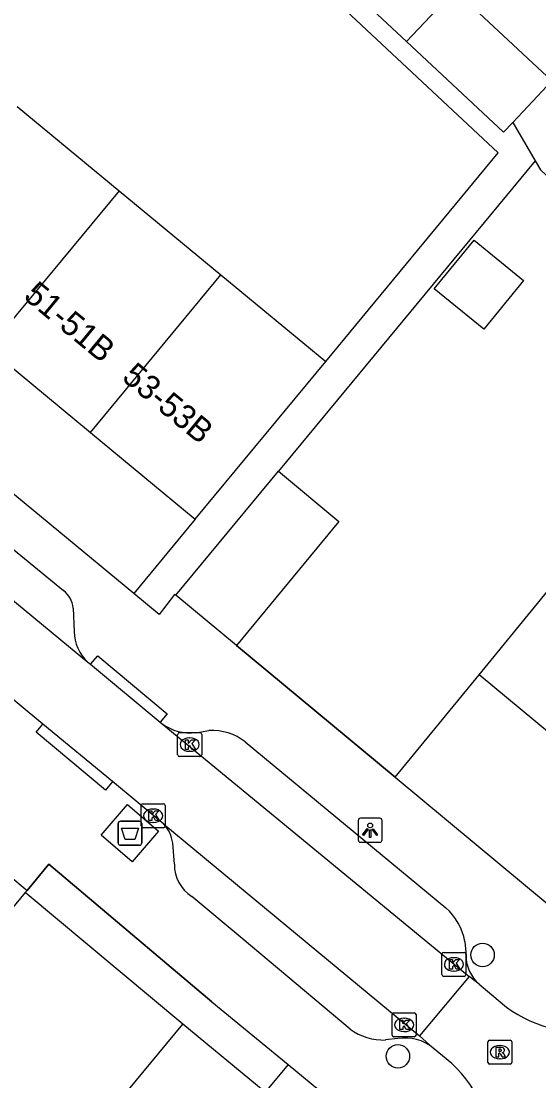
# Model space of a CAD drawing. Extents: x 162074 to 163034, y 381824 to 382557.
# Drawn here: x 162580.7 to 162602.27, y 382130.62 to 382174.8 of the extents above; entities that cross this region are included whole.
import ezdxf

# ---------------------------------------------------------------- set-up
doc = ezdxf.new("R2010")
doc.units = 0
for name, color, linetype in [('IMGEO_Afval_apart_plaats', 7, 'Continuous'), ('IMGEO_Boom', 7, 'Continuous'), ('IMGEO_Kolk', 7, 'Continuous'), ('IMGEO_Lichtpunt', 7, 'Continuous'), ('IMGEO_Muur', 7, 'Continuous'), ('IMGEO_Pand', 7, 'Continuous'), ('IMGEO_Pand_nummerreeks', 7, 'Continuous'), ('IMGEO_Rijbaan_lokaal_open', 7, 'Continuous'), ('IMGEO_Rioolput', 7, 'Continuous'), ('IMGEO_Voetpad_gesloten', 7, 'Continuous'), ('IMGEO_Voetpad_open', 7, 'Continuous')]:
    doc.layers.add(name, color=color, linetype=linetype)

msp = doc.modelspace()

# ---------------------------------------------------------------- linework, layer by layer
at = {"layer": 'IMGEO_Afval_apart_plaats'}
for p, q in [((162584.736, 382140.54), (162584.736, 382141.34)), ((162584.736, 382141.34), (162584.736, 382140.54)), ((162584.836, 382141.44), (162585.626, 382141.44)), ((162585.626, 382141.44), (162584.836, 382141.44)), ((162585.726, 382141.34), (162585.726, 382140.54)), ((162585.726, 382140.54), (162585.726, 382141.34)), ((162585.626, 382140.44), (162584.836, 382140.44)), ((162584.836, 382140.44), (162585.626, 382140.44))]:
    msp.add_line(p, q, dxfattribs=at)
msp.add_lwpolyline([(162584.879, 382141.154), (162585.583, 382141.154), (162585.434, 382140.684), (162585.028, 382140.684), (162584.879, 382141.154)], dxfattribs=at)
for centre, start, end in [((162584.836, 382141.34), 90, 180), ((162584.836, 382141.34), 90, 180), ((162585.626, 382141.34), 0, 90), ((162585.626, 382141.34), 360, 90), ((162584.836, 382140.54), 180, 270), ((162584.836, 382140.54), 180, 270), ((162585.626, 382140.54), 270, 0), ((162585.626, 382140.54), 270, 0)]:
    msp.add_arc(centre, 0.1, start, end, dxfattribs=at)
at = {"layer": 'IMGEO_Boom'}
for centre in [(162599.932, 382135.864), (162596.402, 382131.638)]:
    msp.add_circle(centre, 0.489, dxfattribs=at)
at = {"layer": 'IMGEO_Kolk'}
for p, q in [((162587.297, 382145.137), (162588.149, 382145.137)), ((162587.222, 382144.211), (162587.222, 382145.063)), ((162587.71, 382144.917), (162587.735, 382144.917)), ((162588.223, 382145.063), (162588.223, 382144.211)), ((162587.733, 382144.357), (162587.708, 382144.357)), ((162588.149, 382144.137), (162587.297, 382144.137)), ((162585.704, 382141.243), (162585.704, 382142.095)), ((162585.779, 382142.169), (162586.631, 382142.169)), ((162586.705, 382142.095), (162586.705, 382141.243)), ((162586.192, 382141.949), (162586.217, 382141.949)), ((162586.631, 382141.169), (162585.779, 382141.169)), ((162586.215, 382141.389), (162586.19, 382141.389)), ((162598.238, 382135.045), (162598.238, 382135.897)), ((162598.313, 382135.971), (162599.165, 382135.971)), ((162599.239, 382135.897), (162599.239, 382135.045)), ((162598.726, 382135.751), (162598.751, 382135.751)), ((162599.165, 382134.971), (162598.313, 382134.971)), ((162598.749, 382135.191), (162598.724, 382135.191)), ((162596.158, 382132.523), (162596.158, 382133.375)), ((162596.233, 382133.449), (162597.085, 382133.449)), ((162596.646, 382133.229), (162596.671, 382133.229)), ((162597.159, 382133.375), (162597.159, 382132.523)), ((162597.085, 382132.449), (162596.233, 382132.449)), ((162596.669, 382132.669), (162596.644, 382132.669))]:
    msp.add_line(p, q, dxfattribs=at)
for points in [[(162587.297, 382145.137), (162588.149, 382145.137)], [(162587.222, 382144.211), (162587.222, 382145.063)], [(162587.543, 382144.837), (162587.666, 382144.837), (162587.666, 382144.686), (162587.796, 382144.837), (162587.96, 382144.837), (162587.814, 382144.686), (162587.967, 382144.437), (162587.815, 382144.437), (162587.73, 382144.601), (162587.666, 382144.534), (162587.666, 382144.437), (162587.543, 382144.437), (162587.543, 382144.837)], [(162588.223, 382145.063), (162588.223, 382144.211)], [(162588.149, 382144.137), (162587.297, 382144.137)], [(162585.704, 382141.243), (162585.704, 382142.095)], [(162585.779, 382142.169), (162586.631, 382142.169)], [(162586.705, 382142.095), (162586.705, 382141.243)], [(162586.025, 382141.869), (162586.148, 382141.869), (162586.148, 382141.718), (162586.278, 382141.869), (162586.442, 382141.869), (162586.296, 382141.718), (162586.449, 382141.469), (162586.297, 382141.469), (162586.212, 382141.633), (162586.148, 382141.566), (162586.148, 382141.469), (162586.025, 382141.469), (162586.025, 382141.869)], [(162586.631, 382141.169), (162585.779, 382141.169)], [(162598.238, 382135.045), (162598.238, 382135.897)], [(162598.313, 382135.971), (162599.165, 382135.971)], [(162599.239, 382135.897), (162599.239, 382135.045)], [(162598.559, 382135.671), (162598.682, 382135.671), (162598.682, 382135.52), (162598.812, 382135.671), (162598.976, 382135.671), (162598.83, 382135.52), (162598.983, 382135.271), (162598.831, 382135.271), (162598.746, 382135.435), (162598.682, 382135.368), (162598.682, 382135.271), (162598.559, 382135.271), (162598.559, 382135.671)], [(162599.165, 382134.971), (162598.313, 382134.971)], [(162596.158, 382132.523), (162596.158, 382133.375)], [(162596.233, 382133.449), (162597.085, 382133.449)], [(162596.479, 382133.149), (162596.602, 382133.149), (162596.602, 382132.998), (162596.732, 382133.149), (162596.896, 382133.149), (162596.75, 382132.998), (162596.903, 382132.749), (162596.751, 382132.749), (162596.666, 382132.913), (162596.602, 382132.846), (162596.602, 382132.749), (162596.479, 382132.749), (162596.479, 382133.149)], [(162597.159, 382133.375), (162597.159, 382132.523)], [(162597.085, 382132.449), (162596.233, 382132.449)]]:
    msp.add_lwpolyline(points, dxfattribs=at)
for centre, start, end in [((162587.299, 382145.061), 91.552, 178.448), ((162587.299, 382145.061), 91.552, 178.448), ((162588.147, 382145.061), 1.552, 88.448), ((162588.147, 382145.061), 1.552, 88.448), ((162587.299, 382144.213), 181.552, 268.448), ((162587.299, 382144.213), 181.552, 268.448), ((162588.147, 382144.213), 271.552, 358.448), ((162588.147, 382144.213), 271.552, 358.448), ((162585.781, 382142.093), 91.552, 178.448), ((162585.781, 382142.093), 91.552, 178.448), ((162586.629, 382142.093), 1.552, 88.448), ((162586.629, 382142.093), 1.552, 88.448), ((162585.781, 382141.245), 181.552, 268.448), ((162585.781, 382141.245), 181.552, 268.448), ((162586.629, 382141.245), 271.552, 358.448), ((162586.629, 382141.245), 271.552, 358.448), ((162598.315, 382135.895), 91.552, 178.448), ((162598.315, 382135.895), 91.552, 178.448), ((162599.163, 382135.895), 1.552, 88.448), ((162599.163, 382135.895), 1.552, 88.448), ((162598.315, 382135.047), 181.552, 268.448), ((162598.315, 382135.047), 181.552, 268.448), ((162599.163, 382135.047), 271.552, 358.448), ((162599.163, 382135.047), 271.552, 358.448), ((162596.235, 382133.373), 91.552, 178.448), ((162596.235, 382133.373), 91.552, 178.448), ((162597.083, 382133.373), 1.552, 88.448), ((162597.083, 382133.373), 1.552, 88.448), ((162596.235, 382132.525), 181.552, 268.448), ((162596.235, 382132.525), 181.552, 268.448), ((162597.083, 382132.525), 271.552, 358.448), ((162597.083, 382132.525), 271.552, 358.448)]:
    msp.add_arc(centre, 0.0765, start, end, dxfattribs=at)
for centre, major_axis, ratio, start_param, end_param in [((162587.709, 382144.637), (-0.387, 0.002), 0.722429, 4.712389, 7.853982), ((162587.734, 382144.637), (-0.39, 0.002), 0.717154, 1.570796, 4.712389), ((162586.191, 382141.669), (-0.387, 0.002), 0.722429, 4.712389, 7.853982), ((162586.216, 382141.669), (-0.39, 0.002), 0.717154, 1.570796, 4.712389), ((162598.725, 382135.471), (-0.387, 0.002), 0.722429, 4.712389, 7.853982), ((162598.75, 382135.471), (-0.39, 0.002), 0.717154, 1.570796, 4.712389), ((162596.645, 382132.949), (-0.387, 0.002), 0.722429, 4.712389, 7.853982), ((162596.67, 382132.949), (-0.39, 0.002), 0.717154, 1.570796, 4.712389)]:
    msp.add_ellipse(centre, major_axis=major_axis, ratio=ratio, start_param=start_param, end_param=end_param, dxfattribs=at)
at = {"layer": 'IMGEO_Lichtpunt'}
for p, q in [((162595.648, 382141.562), (162594.84, 382141.562)), ((162595.648, 382141.562), (162594.84, 382141.562)), ((162594.746, 382141.467), (162594.746, 382140.66)), ((162594.746, 382141.467), (162594.746, 382140.66)), ((162595.742, 382140.66), (162595.742, 382141.467)), ((162595.742, 382140.66), (162595.742, 382141.467)), ((162594.84, 382140.566), (162595.648, 382140.566)), ((162594.84, 382140.566), (162595.648, 382140.566))]:
    msp.add_line(p, q, dxfattribs=at)
for points in [[(162595.12, 382141.131), (162595.159, 382141.103), (162594.971, 382140.841), (162594.933, 382140.868), (162595.12, 382141.131)], [(162595.332, 382141.103), (162595.37, 382141.13), (162595.557, 382140.868), (162595.518, 382140.84), (162595.332, 382141.103)], [(162595.222, 382141.083), (162595.269, 382141.083), (162595.269, 382140.761), (162595.222, 382140.761), (162595.222, 382141.083)]]:
    msp.add_lwpolyline(points, dxfattribs=at)
msp.add_circle((162595.245, 382141.265), 0.0994, dxfattribs=at)
for centre, start, end in [((162594.84, 382141.467), 90, 180), ((162594.84, 382141.467), 90, 180), ((162595.648, 382141.467), 0, 90), ((162595.648, 382141.467), 0, 90), ((162594.84, 382140.66), 180, 270), ((162594.84, 382140.66), 180, 270), ((162595.648, 382140.66), 270, 0), ((162595.648, 382140.66), 270, 360)]:
    msp.add_arc(centre, 0.0946, start, end, dxfattribs=at)
at = {"layer": 'IMGEO_Muur'}
for points in [[(162596.289, 382143.28), (162589.673, 382148.769)], [(162588.643, 382133.909), (162581.857, 382139.648), (162580.943, 382138.549)]]:
    msp.add_lwpolyline(points, dxfattribs=at)
at = {"layer": 'IMGEO_Pand'}
for points in [[(162596.764, 382173.95), (162592.721, 382177.733)], [(162598.774, 382176.098), (162596.764, 382173.95)], [(162598.774, 382176.098), (162602.817, 382172.315)], [(162596.764, 382173.95), (162600.807, 382170.167), (162601.197, 382170.583)], [(162602.817, 382172.315), (162601.812, 382171.241), (162601.197, 382170.583)], [(162602.128, 382168.98), (162602.35, 382168.598), (162603.029, 382167.963), (162605.932, 382171.065), (162605.08, 382171.863), (162602.817, 382172.315)], [(162580.53, 382171.244), (162584.777, 382167.732)], [(162601.197, 382170.583), (162602.128, 382168.98)], [(162584.777, 382167.732), (162579.338, 382161.16)], [(162584.777, 382167.732), (162589.023, 382164.22)], [(162597.919, 382163.646), (162599.578, 382165.671), (162601.641, 382163.982), (162599.982, 382161.956), (162597.919, 382163.646)], [(162583.585, 382157.648), (162589.023, 382164.22)], [(162589.023, 382164.22), (162593.393, 382160.606)], [(162579.338, 382161.16), (162583.585, 382157.648)], [(162587.956, 382154.032), (162593.393, 382160.606)], [(162583.585, 382157.648), (162587.956, 382154.032)], [(162587.149, 382150.868), (162591.419, 382156.031)], [(162591.419, 382156.031), (162593.943, 382153.932), (162589.673, 382148.769)], [(162599.784, 382147.547), (162603.279, 382151.815)], [(162589.673, 382148.769), (162587.149, 382150.868)], [(162596.289, 382143.28), (162599.784, 382147.547)], [(162607.287, 382143.348), (162604.281, 382145.835), (162603.295, 382144.643), (162599.784, 382147.547)], [(162596.289, 382143.28), (162602.791, 382137.875)], [(162578.638, 382140.471), (162580.943, 382138.549)], [(162580.871, 382138.462), (162576.913, 382133.681), (162574.608, 382135.603)], [(162580.871, 382138.462), (162580.943, 382138.549)], [(162583.835, 382128.631), (162587.435, 382132.983)], [(162591.826, 382131.301), (162590.868, 382130.143), (162587.435, 382132.983)], [(162591.826, 382131.301), (162594.946, 382128.72)]]:
    msp.add_lwpolyline(points, dxfattribs=at)
at = {"layer": 'IMGEO_Rijbaan_lokaal_open'}
for points in [[(162455.575, 382254.047), (162467.743, 382243.863), (162583.48, 382148.075)], [(162581.599, 382145.482), (162576.743, 382149.513)], [(162583.48, 382148.075), (162583.59, 382147.984)], [(162583.59, 382147.984), (162586.493, 382145.572)], [(162586.493, 382145.572), (162586.579, 382145.506)], [(162584.507, 382143.092), (162581.599, 382145.482)], [(162586.579, 382145.506), (162599.371, 382134.967)], [(162586.648, 382141.318), (162584.507, 382143.092)], [(162586.648, 382141.318), (162597.298, 382132.492)], [(162599.371, 382134.967), (162597.298, 382132.492)], [(162599.786, 382134.645), (162599.371, 382134.967)], [(162599.786, 382134.645), (162600.923, 382133.683)], [(162597.298, 382132.492), (162597.874, 382131.979)], [(162598.653, 382131.338), (162597.874, 382131.979)]]:
    msp.add_lwpolyline(points, dxfattribs=at)
for centre, radius, start, end in [((162604.179, 382138.227), 5.59, 234.3736, 323.6831), ((162594.493, 382127.015), 6, 321.0212, 46.1023)]:
    msp.add_arc(centre, radius, start, end, dxfattribs=at)
at = {"layer": 'IMGEO_Rioolput'}
for p, q in [((162600.226, 382132.31), (162601.078, 382132.31)), ((162600.151, 382131.384), (162600.151, 382132.236)), ((162600.639, 382132.09), (162600.664, 382132.09)), ((162601.152, 382132.236), (162601.152, 382131.384)), ((162600.662, 382131.53), (162600.637, 382131.53)), ((162601.078, 382131.31), (162600.226, 382131.31))]:
    msp.add_line(p, q, dxfattribs=at)
for points in [[(162600.226, 382132.31), (162601.078, 382132.31)], [(162600.151, 382131.384), (162600.151, 382132.236)], [(162600.74, 382132.008), (162600.488, 382132.01), (162600.488, 382131.61)], [(162600.666, 382131.929), (162600.612, 382131.929), (162600.612, 382131.848)], [(162600.612, 382131.848), (162600.664, 382131.848)], [(162601.152, 382132.236), (162601.152, 382131.384)], [(162600.488, 382131.61), (162600.612, 382131.61), (162600.612, 382131.772), (162600.623, 382131.772)], [(162600.67, 382131.743), (162600.741, 382131.61), (162600.881, 382131.61), (162600.816, 382131.736)], [(162601.078, 382131.31), (162600.226, 382131.31)]]:
    msp.add_lwpolyline(points, dxfattribs=at)
for centre, radius, start, end in [((162600.228, 382132.234), 0.0765, 91.552, 178.448), ((162600.228, 382132.234), 0.0765, 91.552, 178.448), ((162601.076, 382132.234), 0.0765, 1.552, 88.448), ((162601.076, 382132.234), 0.0765, 1.552, 88.448), ((162600.648, 382132.037), 0.19, 274.7715, 282.9687), ((162600.672, 382131.833), 0.0964, 77.0061, 93.1865), ((162600.686, 382131.89), 0.0378, 276.6634, 79.6772), ((162600.739, 382131.898), 0.109, 350.3612, 89.416), ((162600.737, 382131.898), 0.112, 277.5842, 350.9817), ((162600.228, 382131.386), 0.0765, 181.552, 268.448), ((162600.228, 382131.386), 0.0765, 181.552, 268.448), ((162600.622, 382131.719), 0.0533, 26.0293, 88.6989), ((162600.721, 382131.683), 0.108, 29.5134, 73.7905), ((162601.076, 382131.386), 0.0765, 271.552, 358.448), ((162601.076, 382131.386), 0.0765, 271.552, 358.448)]:
    msp.add_arc(centre, radius, start, end, dxfattribs=at)
for centre, major_axis, ratio, start_param, end_param in [((162600.638, 382131.81), (-0.387, 0.002), 0.722429, 4.712389, 7.853982), ((162600.663, 382131.81), (-0.39, 0.002), 0.717154, 1.570796, 4.712389)]:
    msp.add_ellipse(centre, major_axis=major_axis, ratio=ratio, start_param=start_param, end_param=end_param, dxfattribs=at)
at = {"layer": 'IMGEO_Voetpad_gesloten'}
msp.add_lwpolyline([(162585.133, 382142.134), (162586.427, 382141.019), (162585.329, 382139.745), (162584.035, 382140.86), (162585.133, 382142.134)], dxfattribs=at)
at = {"layer": 'IMGEO_Voetpad_open'}
for points in [[(162593.393, 382160.606), (162600.588, 382169.306), (162548.041, 382218.424), (162538.119, 382206.437)], [(162585.394, 382150.935), (162530.074, 382196.697)], [(162602.128, 382168.98), (162591.419, 382156.031)], [(162575.482, 382156.776), (162582.465, 382151.06)], [(162587.956, 382154.032), (162585.394, 382150.935)], [(162587.149, 382150.868), (162587.088, 382150.899), (162586.457, 382150.056), (162585.394, 382150.935)], [(162582.87, 382150.33), (162582.909, 382149.358)], [(162589.673, 382148.769), (162596.289, 382143.28)], [(162583.59, 382147.984), (162583.899, 382148.341), (162586.79, 382145.923), (162586.493, 382145.572)], [(162584.507, 382143.092), (162584.217, 382142.737), (162581.329, 382145.157), (162581.599, 382145.482)], [(162587.978, 382145.133), (162588.527, 382145.218)], [(162590.037, 382144.749), (162598.401, 382137.832)], [(162587.085, 382139.65), (162587.018, 382140.526)], [(162580.943, 382138.549), (162581.857, 382139.648), (162588.643, 382133.909), (162591.826, 382131.301)], [(162587.435, 382132.983), (162580.871, 382138.462)], [(162594.41, 382132.775), (162589.908, 382136.549), (162587.807, 382138.304)], [(162599.19, 382136.425), (162599.241, 382135.827)], [(162596.401, 382132.375), (162595.886, 382132.318)]]:
    msp.add_lwpolyline(points, dxfattribs=at)
for centre, radius, start, end in [((162581.809, 382150.219), 1.067, 5.9914, 52.0511), ((162584.635, 382149.357), 1.726, 179.9825, 228.0004), ((162587.757, 382147.113), 1.992, 233.7601, 276.3822), ((162588.669, 382143.009), 2.214, 51.8223, 93.6685), ((162585.556, 382140.325), 1.476, 7.8126, 42.2687), ((162588.652, 382139.624), 1.567, 179.0491, 237.3695), ((162596.745, 382135.979), 2.485, 10.3444, 48.2202), ((162600.842, 382135.848), 1.601, 180.7666, 228.7406), ((162595.8, 382134.653), 2.337, 233.4882, 272.1046), ((162596.709, 382130.584), 1.818, 50.144, 99.7609)]:
    msp.add_arc(centre, radius, start, end, dxfattribs=at)

# ---------------------------------------------------------------- texts
at = {"layer": 'IMGEO_Pand_nummerreeks'}
for s, p in [('51-51B', (162580.752, 382163.261)), ('53-53B', (162584.85, 382159.872))]:
    msp.add_text(s, height=1, rotation=320.4088, dxfattribs=at).set_placement(p)

doc.saveas('drawing.dxf')
